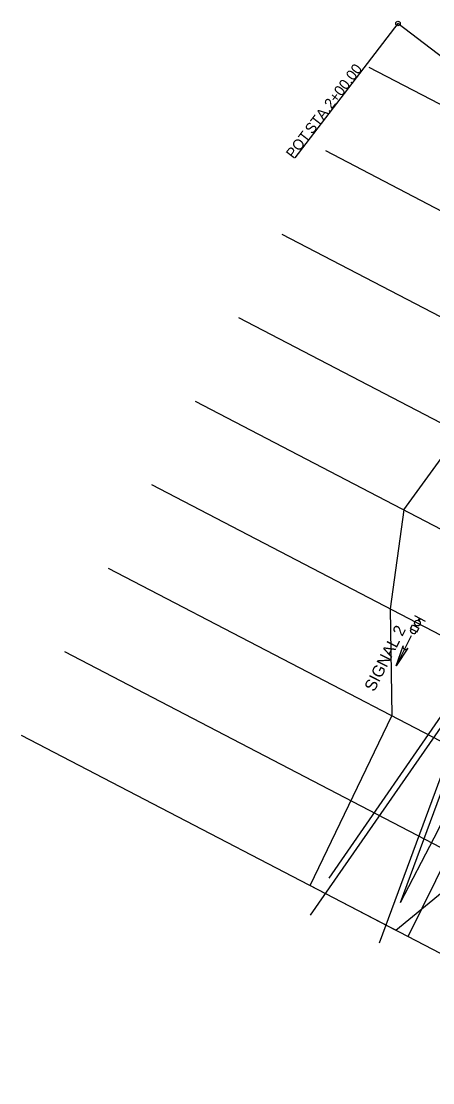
# Model space of a CAD drawing. Extents: x 2034057 to 2035954, y 247386 to 249135.
# Drawn here: x 2034056.7 to 2034166.1, y 247621.4 to 247903.4 of the extents above; entities that cross this region are included whole.
import ezdxf

# ---------------------------------------------------------------- set-up
doc = ezdxf.new("R2010")
doc.units = 0
for name, color, linetype in [('_CIVIL_CONSTRUCTION', 7, 'Continuous'), ('Default', 7, 'Continuous'), ('DR_X_Text', 7, 'Continuous'), ('PV_X_Driveway', 7, 'Continuous'), ('RD_X_GR_Lt', 7, 'Continuous'), ('RD_X_GR_Rt', 7, 'Continuous'), ('RS_Raster1', 7, 'Continuous'), ('RW_X_CL_100_Stations', 7, 'Continuous'), ('SC_Scratch1', 7, 'Continuous'), ('XS_X_Ground_Line', 7, 'Continuous')]:
    doc.layers.add(name, color=color, linetype=linetype)

msp = doc.modelspace()

# ---------------------------------------------------------------- linework, layer by layer
at = {"layer": '_CIVIL_CONSTRUCTION'}
msp.add_line((2034315.48, 247781.01), (2034156.82, 247902.78), dxfattribs=at)
at = {"layer": 'Default'}
for p, q in [((2034149.07, 247891.18), (2034326.47, 247798.82)), ((2034137.53, 247869), (2034314.92, 247776.64)), ((2034125.98, 247846.83), (2034303.38, 247754.47)), ((2034114.43, 247824.66), (2034291.83, 247732.29)), ((2034102.89, 247802.48), (2034280.28, 247710.12)), ((2034091.34, 247780.31), (2034268.74, 247687.94)), ((2034079.8, 247758.13), (2034257.19, 247665.77)), ((2034068.25, 247735.96), (2034245.65, 247643.6)), ((2034056.71, 247713.78), (2034234.1, 247621.42))]:
    msp.add_line(p, q, dxfattribs=at)
at = {"layer": 'DR_X_Text'}
msp.add_lwpolyline([(2034159.51, 247660.26), (2034170.62, 247682.66), (2034171.93, 247687.34)], dxfattribs=at)
at = {"layer": 'PV_X_Driveway'}
msp.add_line((2034191.69, 247761.92), (2034157.41, 247669.23), dxfattribs=at)
at = {"layer": 'RD_X_GR_Lt'}
msp.add_line((2034204.76, 247768.61), (2034133.48, 247665.92), dxfattribs=at)
msp.add_lwpolyline([(2034188.71, 247729.61), (2034177.8, 247708.67), (2034166.36, 247686.43), (2034157.41, 247669.23)], dxfattribs=at)
at = {"layer": 'RD_X_GR_Rt'}
for p, q in [((2034161.18, 247745.51), (2034164.07, 247744.05)), ((2034161.18, 247745.51), (2034164.07, 247744.05)), ((2034160.15, 247742.04), (2034160.67, 247743.06)), ((2034160.15, 247742.04), (2034160.67, 247743.06)), ((2034160.67, 247743.06), (2034162.4, 247742.18)), ((2034160.67, 247743.06), (2034162.4, 247742.18)), ((2034161.55, 247742.91), (2034161.43, 247742.67)), ((2034161.55, 247742.91), (2034161.43, 247742.67)), ((2034161.76, 247742.8), (2034161.64, 247742.57)), ((2034161.76, 247742.8), (2034161.64, 247742.57)), ((2034162.52, 247744.84), (2034162.22, 247744.25)), ((2034162.52, 247744.84), (2034162.22, 247744.25)), ((2034162.73, 247744.73), (2034162.43, 247744.14)), ((2034162.73, 247744.73), (2034162.43, 247744.14)), ((2034160.35, 247740.13), (2034156.3, 247732.15)), ((2034160.15, 247742.04), (2034161.88, 247741.16)), ((2034160.15, 247742.04), (2034161.88, 247741.16)), ((2034160.15, 247741.49), (2034160.37, 247741.92)), ((2034160.15, 247741.49), (2034160.37, 247741.92)), ((2034161.44, 247740.83), (2034161.66, 247741.27)), ((2034161.44, 247740.83), (2034161.66, 247741.27)), ((2034161.88, 247741.16), (2034162.4, 247742.18)), ((2034161.88, 247741.16), (2034162.4, 247742.18)), ((2034156.3, 247732.15), (2034158.22, 247737.49)), ((2034159.47, 247736.85), (2034156.3, 247732.15))]:
    msp.add_line(p, q, dxfattribs=at)
msp.add_circle((2034161.99, 247743.52), 0.757, dxfattribs=at)
msp.add_circle((2034161.99, 247743.52), 0.757, dxfattribs=at)
msp.add_circle((2034161.99, 247743.52), 0.757, dxfattribs=at)
msp.add_circle((2034161.99, 247743.52), 0.757, dxfattribs=at)
msp.add_circle((2034161.99, 247743.52), 0.757, dxfattribs=at)
msp.add_circle((2034161.99, 247743.52), 0.757, dxfattribs=at)
msp.add_circle((2034161.99, 247743.52), 0.757, dxfattribs=at)
msp.add_circle((2034161.99, 247743.52), 0.757, dxfattribs=at)
msp.add_circle((2034161.99, 247743.52), 0.757, dxfattribs=at)
msp.add_circle((2034161.99, 247743.52), 0.757, dxfattribs=at)
msp.add_circle((2034161.99, 247743.52), 0.757, dxfattribs=at)
msp.add_circle((2034161.99, 247743.52), 0.757, dxfattribs=at)
msp.add_arc((2034158.84, 247737.17), 0.703, 153.0802, 333.0802, dxfattribs=at)
msp.add_ellipse((2034160.8, 247741.16), major_axis=(-0.643, 0.325), ratio=0.45371, start_param=0, end_param=3.141593, dxfattribs=at)
msp.add_ellipse((2034160.8, 247741.16), major_axis=(-0.643, 0.325), ratio=0.45371, start_param=0, end_param=3.141593, dxfattribs=at)
at = {"layer": 'RS_Raster1'}
msp.add_line((2034151.87, 247658.6), (2034196.67, 247779.59), dxfattribs=at)
at = {"layer": 'RW_X_CL_100_Stations'}
msp.add_line((2034156.82, 247902.78), (2034129.42, 247867.08), dxfattribs=at)
msp.add_circle((2034156.82, 247902.78), 0.6, dxfattribs=at)
at = {"layer": 'SC_Scratch1'}
msp.add_line((2034138.55, 247675.74), (2034192.77, 247754.24), dxfattribs=at)
at = {"layer": 'XS_X_Ground_Line'}
msp.add_line((2034133.48, 247673.81), (2034155.15, 247718.9), dxfattribs=at)
for points in [[(2034158.38, 247773.59), (2034173.22, 247794.05), (2034188.39, 247813.42)], [(2034158.38, 247773.59), (2034154.77, 247747.28), (2034155.15, 247718.9)], [(2034133.48, 247673.81), (2034156.29, 247661.93), (2034179.88, 247681.38)]]:
    msp.add_lwpolyline(points, dxfattribs=at)

# ---------------------------------------------------------------- texts
at = {"layer": 'RD_X_GR_Rt'}
msp.add_text('SIGNAL 2', height=3.125, rotation=63.0802, dxfattribs=at).set_placement((2034150.51, 247725.11))
at = {"layer": 'RW_X_CL_100_Stations'}
for s, p in [('2+00.00', (2034139.19, 247879.87)), (' STA. ', (2034133.43, 247872.37)), ('POT', (2034129.05, 247866.65))]:
    msp.add_text(s, height=2.8, rotation=52.4956, dxfattribs=at).set_placement(p)

doc.saveas('drawing.dxf')
